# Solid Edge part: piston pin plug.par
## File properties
Author: Robert a Rhodes jr
Template: Normal.par
Last saved by: CADCIM
Revision: 6
Application: Solid Edge
Accuracy: 0.99
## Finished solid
Body 1: solid body, 6 faces, 5 edges, 0 vertices.
  Faces by surface: plane 3, cylinder 2, torus 1
  Edges by curve: circle 5
Bounding box of the edges (mm; curved faces can reach further): 22.000 x 22.000 x 15.000, from (-11, -11, -12) to (11, 11, 3).
Cylindrical faces by radius (mm): R5.5 x1, R11 x1
Toroidal faces (ring radius, tube radius in mm): R9 r2 x1
Planar faces by outward normal: +z 1, -z 2
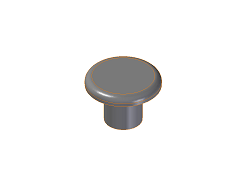
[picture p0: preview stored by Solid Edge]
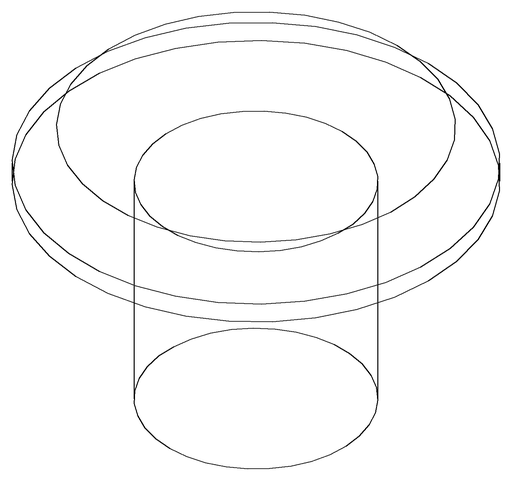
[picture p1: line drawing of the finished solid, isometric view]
